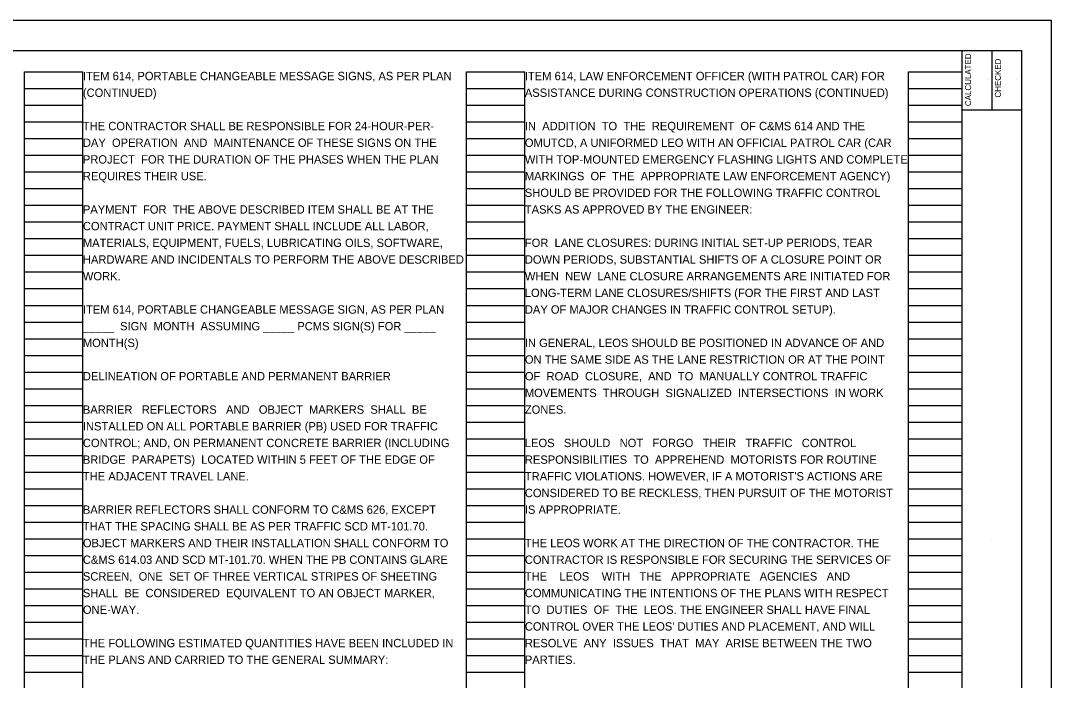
# Model space of a CAD drawing. Extents: x 0 to 34, y 0 to 22.
# Drawn here: x 16.69 to 34, y 10.92 to 22 of the extents above; entities that cross this region are included whole.
import ezdxf

# ---------------------------------------------------------------- set-up
doc = ezdxf.new("R2010")
doc.units = 0
for name, color, linetype in [('SH_Border', 7, 'Continuous'), ('SH_Cut_Line', 7, 'Continuous'), ('SH_Data', 7, 'Continuous'), ('SH_Text', 7, 'Continuous'), ('TX_P_1', 7, 'Continuous')]:
    doc.layers.add(name, color=color, linetype=linetype)

msp = doc.modelspace()

# ---------------------------------------------------------------- linework, layer by layer
at = {"layer": 'SH_Border'}
for p, q in [((32.5, 0.5), (32.5, 21.5)), ((33, 21.5), (33, 20.5)), ((32.5, 20.5), (33.5, 20.5))]:
    msp.add_line(p, q, dxfattribs=at)
msp.add_lwpolyline([(2, 21.5), (33.5, 21.5), (33.5, 0.5), (2, 0.5)], close=True, dxfattribs=at)
at = {"layer": 'SH_Cut_Line'}
msp.add_lwpolyline([(0, 0), (34, 0), (34, 22), (0, 22)], close=True, dxfattribs=at)
at = {"layer": 'SH_Data'}
for p, q in [((16.76, 0.98), (16.76, 21.14)), ((16.76, 21.14), (17.74, 21.14)), ((17.74, 0.98), (17.74, 21.14)), ((24.18, 0.98), (24.18, 21.14)), ((24.18, 21.14), (25.16, 21.14)), ((25.16, 0.98), (25.16, 21.14)), ((31.6, 0.98), (31.6, 21.14)), ((31.6, 21.14), (32.5, 21.14)), ((32.5, 0.98), (32.5, 21.14)), ((32.92, 21.004), (32.92, 21.004)), ((33.42, 21.004), (33.42, 21.004)), ((16.76, 20.86), (17.74, 20.86)), ((24.18, 20.86), (25.16, 20.86)), ((31.6, 20.86), (32.5, 20.86)), ((16.76, 20.58), (17.74, 20.58)), ((24.18, 20.58), (25.16, 20.58)), ((31.6, 20.58), (32.5, 20.58)), ((16.76, 20.3), (17.74, 20.3)), ((24.18, 20.3), (25.16, 20.3)), ((31.6, 20.3), (32.5, 20.3)), ((16.76, 20.02), (17.74, 20.02)), ((24.18, 20.02), (25.16, 20.02)), ((31.6, 20.02), (32.5, 20.02)), ((16.76, 19.74), (17.74, 19.74)), ((24.18, 19.74), (25.16, 19.74)), ((31.6, 19.74), (32.5, 19.74)), ((16.76, 19.46), (17.74, 19.46)), ((24.18, 19.46), (25.16, 19.46)), ((31.6, 19.46), (32.5, 19.46)), ((16.76, 19.18), (17.74, 19.18)), ((24.18, 19.18), (25.16, 19.18)), ((31.6, 19.18), (32.5, 19.18)), ((16.76, 18.9), (17.74, 18.9)), ((24.18, 18.9), (25.16, 18.9)), ((31.6, 18.9), (32.5, 18.9)), ((16.76, 18.62), (17.74, 18.62)), ((24.18, 18.62), (25.16, 18.62)), ((31.6, 18.62), (32.5, 18.62)), ((16.76, 18.34), (17.74, 18.34)), ((24.18, 18.34), (25.16, 18.34)), ((31.6, 18.34), (32.5, 18.34)), ((16.76, 18.06), (17.74, 18.06)), ((24.18, 18.06), (25.16, 18.06)), ((31.6, 18.06), (32.5, 18.06)), ((16.76, 17.78), (17.74, 17.78)), ((24.18, 17.78), (25.16, 17.78)), ((31.6, 17.78), (32.5, 17.78)), ((16.76, 17.5), (17.74, 17.5)), ((24.18, 17.5), (25.16, 17.5)), ((31.6, 17.5), (32.5, 17.5)), ((16.76, 17.22), (17.74, 17.22)), ((24.18, 17.22), (25.16, 17.22)), ((31.6, 17.22), (32.5, 17.22)), ((16.76, 16.94), (17.74, 16.94)), ((24.18, 16.94), (25.16, 16.94)), ((31.6, 16.94), (32.5, 16.94)), ((16.76, 16.66), (17.74, 16.66)), ((24.18, 16.66), (25.16, 16.66)), ((31.6, 16.66), (32.5, 16.66)), ((16.76, 16.38), (17.74, 16.38)), ((24.18, 16.38), (25.16, 16.38)), ((31.6, 16.38), (32.5, 16.38)), ((16.76, 16.1), (17.74, 16.1)), ((24.18, 16.1), (25.16, 16.1)), ((31.6, 16.1), (32.5, 16.1)), ((16.76, 15.82), (17.74, 15.82)), ((24.18, 15.82), (25.16, 15.82)), ((31.6, 15.82), (32.5, 15.82)), ((16.76, 15.54), (17.74, 15.54)), ((24.18, 15.54), (25.16, 15.54)), ((31.6, 15.54), (32.5, 15.54)), ((16.76, 15.26), (17.74, 15.26)), ((24.18, 15.26), (25.16, 15.26)), ((31.6, 15.26), (32.5, 15.26)), ((16.76, 14.98), (17.74, 14.98)), ((24.18, 14.98), (25.16, 14.98)), ((31.6, 14.98), (32.5, 14.98)), ((16.76, 14.7), (17.74, 14.7)), ((24.18, 14.7), (25.16, 14.7)), ((31.6, 14.7), (32.5, 14.7)), ((16.76, 14.42), (17.74, 14.42)), ((24.18, 14.42), (25.16, 14.42)), ((31.6, 14.42), (32.5, 14.42)), ((16.76, 14.14), (17.74, 14.14)), ((24.18, 14.14), (25.16, 14.14)), ((31.6, 14.14), (32.5, 14.14)), ((16.76, 13.86), (17.74, 13.86)), ((24.18, 13.86), (25.16, 13.86)), ((31.6, 13.86), (32.5, 13.86)), ((16.76, 13.58), (17.74, 13.58)), ((24.18, 13.58), (25.16, 13.58)), ((31.6, 13.58), (32.5, 13.58)), ((16.76, 13.3), (17.74, 13.3)), ((24.18, 13.3), (25.16, 13.3)), ((31.6, 13.3), (32.5, 13.3)), ((33, 13.292), (33, 13.292)), ((16.76, 13.02), (17.74, 13.02)), ((24.18, 13.02), (25.16, 13.02)), ((31.6, 13.02), (32.5, 13.02)), ((16.76, 12.74), (17.74, 12.74)), ((24.18, 12.74), (25.16, 12.74)), ((31.6, 12.74), (32.5, 12.74)), ((16.76, 12.46), (17.74, 12.46)), ((24.18, 12.46), (25.16, 12.46)), ((31.6, 12.46), (32.5, 12.46)), ((16.76, 12.18), (17.74, 12.18)), ((24.18, 12.18), (25.16, 12.18)), ((31.6, 12.18), (32.5, 12.18)), ((16.76, 11.9), (17.74, 11.9)), ((24.18, 11.9), (25.16, 11.9)), ((31.6, 11.9), (32.5, 11.9)), ((16.76, 11.62), (17.74, 11.62)), ((24.18, 11.62), (25.16, 11.62)), ((31.6, 11.62), (32.5, 11.62)), ((16.76, 11.34), (17.74, 11.34)), ((24.18, 11.34), (25.16, 11.34)), ((31.6, 11.34), (32.5, 11.34)), ((16.76, 11.06), (17.74, 11.06)), ((24.18, 11.06), (25.16, 11.06)), ((31.6, 11.06), (32.5, 11.06))]:
    msp.add_line(p, q, dxfattribs=at)

# ---------------------------------------------------------------- texts
for s, p in [('CALCULATED', (32.652, 20.565)), ('CHECKED', (33.152, 20.708))]:
    msp.add_text(s, height=0.1, rotation=90, dxfattribs=at).set_placement(p)
at = {"layer": 'SH_Text'}
for s, p in [('ITEM 614, LAW ENFORCEMENT OFFICER (WITH PATROL CAR) FOR', (25.16, 21)), ('ASSISTANCE DURING CONSTRUCTION OPERATIONS (CONTINUED)', (25.16, 20.72)), ('THE CONTRACTOR SHALL BE RESPONSIBLE FOR 24-HOUR-PER-', (17.74, 20.16)), ('IN  ADDITION  TO  THE  REQUIREMENT  OF C&MS 614 AND THE', (25.16, 20.16)), ('DAY  OPERATION  AND  MAINTENANCE OF THESE SIGNS ON THE', (17.74, 19.88)), ('OMUTCD, A UNIFORMED LEO WITH AN OFFICIAL PATROL CAR (CAR', (25.16, 19.88)), ('PROJECT  FOR THE DURATION OF THE PHASES WHEN THE PLAN', (17.74, 19.6)), ('WITH TOP-MOUNTED EMERGENCY FLASHING LIGHTS AND COMPLETE', (25.16, 19.6)), ('REQUIRES THEIR USE.', (17.74, 19.32)), ('MARKINGS  OF  THE  APPROPRIATE LAW ENFORCEMENT AGENCY)', (25.16, 19.32)), ('SHOULD BE PROVIDED FOR THE FOLLOWING TRAFFIC CONTROL', (25.16, 19.04)), ('PAYMENT  FOR  THE ABOVE DESCRIBED ITEM SHALL BE AT THE', (17.74, 18.76)), ('TASKS AS APPROVED BY THE ENGINEER:', (25.16, 18.76)), ('CONTRACT UNIT PRICE. PAYMENT SHALL INCLUDE ALL LABOR,', (17.74, 18.48)), ('MATERIALS, EQUIPMENT, FUELS, LUBRICATING OILS, SOFTWARE,', (17.74, 18.2)), ('FOR  LANE CLOSURES: DURING INITIAL SET-UP PERIODS, TEAR', (25.16, 18.2)), ('HARDWARE AND INCIDENTALS TO PERFORM THE ABOVE DESCRIBED', (17.74, 17.92)), ('DOWN PERIODS, SUBSTANTIAL SHIFTS OF A CLOSURE POINT OR', (25.16, 17.92)), ('WORK.', (17.74, 17.64)), ('WHEN  NEW  LANE CLOSURE ARRANGEMENTS ARE INITIATED FOR', (25.16, 17.64)), ('LONG-TERM LANE CLOSURES/SHIFTS (FOR THE FIRST AND LAST', (25.16, 17.36)), ('ITEM 614, PORTABLE CHANGEABLE MESSAGE SIGN, AS PER PLAN', (17.74, 17.08)), ('DAY OF MAJOR CHANGES IN TRAFFIC CONTROL SETUP).', (25.16, 17.08)), ('_____  SIGN  MONTH  ASSUMING _____ PCMS SIGN(S) FOR _____', (17.74, 16.8)), ('MONTH(S)', (17.74, 16.52)), ('IN GENERAL, LEOS SHOULD BE POSITIONED IN ADVANCE OF AND', (25.16, 16.52)), ('ON THE SAME SIDE AS THE LANE RESTRICTION OR AT THE POINT', (25.16, 16.24)), ('DELINEATION OF PORTABLE AND PERMANENT BARRIER', (17.74, 15.96)), ('OF  ROAD  CLOSURE,  AND  TO  MANUALLY CONTROL TRAFFIC', (25.16, 15.96)), ('MOVEMENTS  THROUGH  SIGNALIZED  INTERSECTIONS  IN WORK', (25.16, 15.68)), ('BARRIER   REFLECTORS   AND   OBJECT  MARKERS  SHALL  BE', (17.74, 15.4)), ('ZONES.', (25.16, 15.4)), ('INSTALLED ON ALL PORTABLE BARRIER (PB) USED FOR TRAFFIC', (17.74, 15.12)), ('CONTROL; AND, ON PERMANENT CONCRETE BARRIER (INCLUDING', (17.74, 14.84)), ('LEOS   SHOULD   NOT   FORGO   THEIR   TRAFFIC   CONTROL', (25.16, 14.84)), ('BRIDGE  PARAPETS)  LOCATED WITHIN 5 FEET OF THE EDGE OF', (17.74, 14.56)), ('RESPONSIBILITIES  TO  APPREHEND  MOTORISTS FOR ROUTINE', (25.16, 14.56)), ('THE ADJACENT TRAVEL LANE.', (17.74, 14.28)), ("TRAFFIC VIOLATIONS. HOWEVER, IF A MOTORIST'S ACTIONS ARE", (25.16, 14.28)), ('CONSIDERED TO BE RECKLESS, THEN PURSUIT OF THE MOTORIST', (25.16, 14)), ('BARRIER REFLECTORS SHALL CONFORM TO C&MS 626, EXCEPT', (17.74, 13.72)), ('IS APPROPRIATE.', (25.16, 13.72)), ('THAT THE SPACING SHALL BE AS PER TRAFFIC SCD MT-101.70.', (17.74, 13.44)), ('OBJECT MARKERS AND THEIR INSTALLATION SHALL CONFORM TO', (17.74, 13.16)), ('THE LEOS WORK AT THE DIRECTION OF THE CONTRACTOR. THE', (25.16, 13.16)), ('C&MS 614.03 AND SCD MT-101.70. WHEN THE PB CONTAINS GLARE', (17.74, 12.88)), ('CONTRACTOR IS RESPONSIBLE FOR SECURING THE SERVICES OF', (25.16, 12.88)), ('SCREEN,  ONE  SET OF THREE VERTICAL STRIPES OF SHEETING', (17.74, 12.6)), ('THE    LEOS    WITH   THE   APPROPRIATE   AGENCIES   AND', (25.16, 12.6)), ('SHALL  BE  CONSIDERED  EQUIVALENT TO AN OBJECT MARKER,', (17.74, 12.32)), ('COMMUNICATING THE INTENTIONS OF THE PLANS WITH RESPECT', (25.16, 12.32)), ('ONE-WAY.', (17.74, 12.04)), ('TO  DUTIES  OF  THE  LEOS. THE ENGINEER SHALL HAVE FINAL', (25.16, 12.04)), ("CONTROL OVER THE LEOS' DUTIES AND PLACEMENT, AND WILL", (25.16, 11.76)), ('THE FOLLOWING ESTIMATED QUANTITIES HAVE BEEN INCLUDED IN', (17.74, 11.48)), ('RESOLVE  ANY  ISSUES  THAT  MAY  ARISE BETWEEN THE TWO', (25.16, 11.48)), ('THE PLANS AND CARRIED TO THE GENERAL SUMMARY:', (17.74, 11.2)), ('PARTIES.', (25.16, 11.2))]:
    msp.add_text(s, height=0.14, dxfattribs=at).set_placement(p)
at = {"layer": 'TX_P_1'}
for s, p in [('ITEM 614, PORTABLE CHANGEABLE MESSAGE SIGNS, AS PER PLAN', (17.74, 21)), ('(CONTINUED)', (17.74, 20.72))]:
    msp.add_text(s, height=0.14, dxfattribs=at).set_placement(p)

doc.saveas('drawing.dxf')
